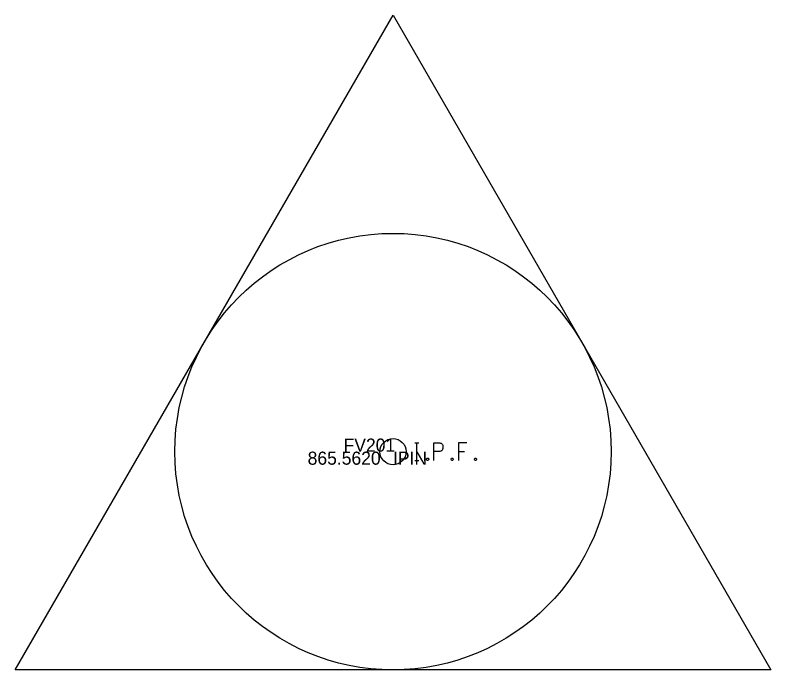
# Model space of a CAD drawing. Extents: x 1479425 to 1480294, y 379351 to 380102.
# Drawn here: x 1479934.507 to 1479937.971, y 379906.271 to 379909.271 of the extents above; entities that cross this region are included whole.
import ezdxf

# ---------------------------------------------------------------- set-up
doc = ezdxf.new("R2010")
doc.units = 0
for name, color, linetype in [('SV_Control_Point', 7, 'Continuous'), ('SV_X_Mon_Cells_Found', 7, 'Continuous'), ('SV_X_Text_Comment', 7, 'Continuous'), ('SV_X_Text_Elevation', 7, 'Continuous'), ('SV_X_Text_Name', 7, 'Continuous')]:
    doc.layers.add(name, color=color, linetype=linetype)

msp = doc.modelspace()

# ---------------------------------------------------------------- linework, layer by layer
at = {"layer": 'SV_Control_Point'}
for p, q in [((1479934.5069, 379906.2711), (1479936.239, 379909.2711)), ((1479936.239, 379909.2711), (1479937.971, 379906.2711)), ((1479936.239, 379907.2711), (1479936.239, 379907.2711)), ((1479937.971, 379906.2711), (1479934.5069, 379906.2711))]:
    msp.add_line(p, q, dxfattribs=at)
msp.add_circle((1479936.239, 379907.2711), 1, dxfattribs=at)
at = {"layer": 'SV_X_Mon_Cells_Found'}
for points in [[(1479936.3397, 379907.3111), (1479936.3574, 379907.3111)], [(1479936.3485, 379907.2311), (1479936.3485, 379907.3111)], [(1479936.4268, 379907.2311), (1479936.4268, 379907.3111), (1479936.4533, 379907.3111), (1479936.456, 379907.3105), (1479936.4599, 379907.3092), (1479936.4615, 379907.308), (1479936.4632, 379907.3067), (1479936.4654, 379907.3036), (1479936.467, 379907.3004), (1479936.4681, 379907.2954), (1479936.4681, 379907.2878), (1479936.4676, 379907.2853), (1479936.4665, 379907.2815), (1479936.4643, 379907.2771), (1479936.4621, 379907.2752), (1479936.4604, 379907.274), (1479936.4577, 379907.2727), (1479936.4533, 379907.2721), (1479936.4268, 379907.2721)], [(1479936.5773, 379907.3111), (1479936.5392, 379907.3111), (1479936.5392, 379907.2311)], [(1479936.5392, 379907.2721), (1479936.5662, 379907.2721)], [(1479936.3397, 379907.2311), (1479936.3574, 379907.2311)], [(1479936.3965, 379907.2418), (1479936.3992, 379907.2418), (1479936.4009, 379907.2406), (1479936.4025, 379907.2381), (1479936.4025, 379907.2349), (1479936.4009, 379907.2324), (1479936.3992, 379907.2311), (1479936.3965, 379907.2311), (1479936.3948, 379907.2324), (1479936.3932, 379907.2349), (1479936.3932, 379907.2381), (1479936.3948, 379907.2406), (1479936.3965, 379907.2418)], [(1479936.5089, 379907.2418), (1479936.5117, 379907.2418), (1479936.5133, 379907.2406), (1479936.515, 379907.2381), (1479936.515, 379907.2349), (1479936.5133, 379907.2324), (1479936.5117, 379907.2311), (1479936.5089, 379907.2311), (1479936.5073, 379907.2324), (1479936.5056, 379907.2349), (1479936.5056, 379907.2381), (1479936.5073, 379907.2406), (1479936.5089, 379907.2418)], [(1479936.6164, 379907.2418), (1479936.6191, 379907.2418), (1479936.6208, 379907.2406), (1479936.6224, 379907.2381), (1479936.6224, 379907.2349), (1479936.6208, 379907.2324), (1479936.6191, 379907.2311), (1479936.6164, 379907.2311), (1479936.6147, 379907.2324), (1479936.6131, 379907.2349), (1479936.6131, 379907.2381), (1479936.6147, 379907.2406), (1479936.6164, 379907.2418)]]:
    msp.add_lwpolyline(points, dxfattribs=at)
msp.add_circle((1479936.239, 379907.2711), 0.06, dxfattribs=at)

# ---------------------------------------------------------------- texts
at = {"layer": 'SV_X_Text_Comment'}
msp.add_text('IPIN', height=0.06, dxfattribs=at).set_placement((1479936.239, 379907.2111))
at = {"layer": 'SV_X_Text_Elevation'}
msp.add_text('865.5620', height=0.06, dxfattribs=at).set_placement((1479935.8478, 379907.2111))
at = {"layer": 'SV_X_Text_Name'}
msp.add_text('FV201', height=0.06, dxfattribs=at).set_placement((1479936.0126, 379907.2711))

doc.saveas('drawing.dxf')
